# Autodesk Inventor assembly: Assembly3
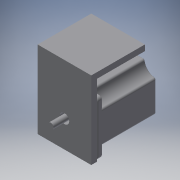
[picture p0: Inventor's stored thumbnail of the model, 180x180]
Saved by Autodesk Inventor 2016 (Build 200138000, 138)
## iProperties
Created: 2016-02
Part Number: Assembly3
Document SubType Name: Assembly
Designer: Juha-Pekka
Author: Juha-Pekka
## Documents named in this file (3)
- C:\Users\Juha-Pekka\Desktop\Assignment2\Assembly3.iam
- C:\Users\Juha-Pekka\Desktop\Assignment2\kulma.ipt
- C:\Users\Juha-Pekka\Desktop\Assignment2\Stepper.ipt
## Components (2 placed, 2 different names)
1. kulma:1
2. Stepper:1
